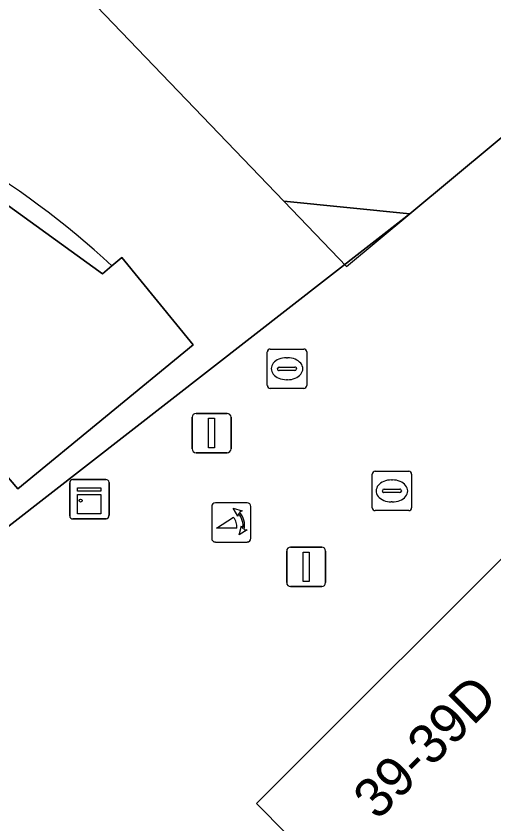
# Model space of a CAD drawing. Extents: x 161087 to 161926, y 382572 to 383873.
# Drawn here: x 161237.04 to 161249.19, y 383157.77 to 383178.3 of the extents above; entities that cross this region are included whole.
import ezdxf

# ---------------------------------------------------------------- set-up
doc = ezdxf.new("R2010")
doc.units = 0
for name, color, linetype in [('IMGEO_Kast', 7, 'Continuous'), ('IMGEO_Kolk', 7, 'Continuous'), ('IMGEO_Lichtmast', 7, 'Continuous'), ('IMGEO_Pand', 7, 'Continuous'), ('IMGEO_Pand_nummerreeks', 7, 'Continuous'), ('IMGEO_Pand_overbouw', 7, 'Continuous'), ('IMGEO_Poller', 7, 'Continuous'), ('IMGEO_Voetgangersgebied_open', 7, 'Continuous')]:
    doc.layers.add(name, color=color, linetype=linetype)

msp = doc.modelspace()

# ---------------------------------------------------------------- linework, layer by layer
at = {"layer": 'IMGEO_Kast'}
for p, q in [((161238.476, 383166.522), (161239.317, 383166.522)), ((161239.317, 383166.522), (161238.476, 383166.522)), ((161238.401, 383165.597), (161238.401, 383166.438)), ((161238.401, 383166.438), (161238.401, 383165.597)), ((161239.401, 383166.447), (161239.401, 383165.606)), ((161239.401, 383165.606), (161239.401, 383166.447)), ((161239.326, 383165.522), (161238.485, 383165.522)), ((161238.485, 383165.522), (161239.326, 383165.522))]:
    msp.add_line(p, q, dxfattribs=at)
for points in [[(161238.596, 383166.312), (161239.196, 383166.312), (161239.196, 383166.227), (161238.596, 383166.227), (161238.596, 383166.312)], [(161238.596, 383166.137), (161239.196, 383166.137), (161239.196, 383165.648), (161238.596, 383165.648), (161238.596, 383166.137)]]:
    msp.add_lwpolyline(points, dxfattribs=at)
msp.add_circle((161238.68, 383165.986), 0.0377, dxfattribs=at)
for centre, start, end in [((161238.479, 383166.444), 92.4484, 184.2845), ((161238.479, 383166.444), 92.4484, 184.2845), ((161239.323, 383166.444), 2.4484, 94.2845), ((161239.323, 383166.444), 2.4484, 94.2845), ((161238.479, 383165.6), 182.4484, 274.2845), ((161238.479, 383165.6), 182.4484, 274.2845), ((161239.323, 383165.6), 272.4484, 4.2845), ((161239.323, 383165.6), 272.4484, 4.2845)]:
    msp.add_arc(centre, 0.0779, start, end, dxfattribs=at)
at = {"layer": 'IMGEO_Kolk'}
for p, q in [((161243.502, 383169.839), (161244.354, 383169.839)), ((161243.427, 383168.913), (161243.427, 383169.765)), ((161243.915, 383169.619), (161243.94, 383169.619)), ((161244.428, 383169.765), (161244.428, 383168.913)), ((161243.686, 383169.333), (161243.686, 383169.345)), ((161244.124, 383169.296), (161243.726, 383169.296)), ((161243.729, 383169.382), (161244.127, 383169.382)), ((161244.17, 383169.345), (161244.17, 383169.333)), ((161243.938, 383169.059), (161243.913, 383169.059)), ((161244.354, 383168.839), (161243.502, 383168.839)), ((161246.169, 383166.732), (161247.021, 383166.732)), ((161246.094, 383165.806), (161246.094, 383166.658)), ((161246.582, 383166.512), (161246.607, 383166.512)), ((161247.095, 383166.658), (161247.095, 383165.806)), ((161246.353, 383166.226), (161246.353, 383166.238)), ((161246.791, 383166.189), (161246.393, 383166.189)), ((161246.396, 383166.275), (161246.794, 383166.275)), ((161246.837, 383166.238), (161246.837, 383166.226)), ((161246.605, 383165.952), (161246.58, 383165.952)), ((161247.021, 383165.732), (161246.169, 383165.732))]:
    msp.add_line(p, q, dxfattribs=at)
for points in [[(161243.502, 383169.839), (161244.354, 383169.839)], [(161243.427, 383168.913), (161243.427, 383169.765)], [(161244.428, 383169.765), (161244.428, 383168.913)], [(161244.354, 383168.839), (161243.502, 383168.839)], [(161246.169, 383166.732), (161247.021, 383166.732)], [(161246.094, 383165.806), (161246.094, 383166.658)], [(161247.095, 383166.658), (161247.095, 383165.806)], [(161247.021, 383165.732), (161246.169, 383165.732)]]:
    msp.add_lwpolyline(points, dxfattribs=at)
for centre, radius, start, end in [((161243.504, 383169.763), 0.0765, 91.552, 178.448), ((161243.504, 383169.763), 0.0765, 91.552, 178.448), ((161244.352, 383169.763), 0.0765, 1.552, 88.448), ((161244.352, 383169.763), 0.0765, 1.552, 88.448), ((161243.726, 383169.342), 0.0403, 85.8775, 175.7526), ((161243.723, 383169.332), 0.0366, 178.938, 274.7102), ((161244.127, 383169.339), 0.043, 264.8664, 352.4533), ((161244.131, 383169.344), 0.0386, 1.7309, 96.639), ((161243.504, 383168.915), 0.0765, 181.552, 268.448), ((161243.504, 383168.915), 0.0765, 181.552, 268.448), ((161244.352, 383168.915), 0.0765, 271.552, 358.448), ((161244.352, 383168.915), 0.0765, 271.552, 358.448), ((161246.171, 383166.656), 0.0765, 91.552, 178.448), ((161246.171, 383166.656), 0.0765, 91.552, 178.448), ((161247.019, 383166.656), 0.0765, 1.552, 88.448), ((161247.019, 383166.656), 0.0765, 1.552, 88.448), ((161246.393, 383166.235), 0.0403, 85.8775, 175.7526), ((161246.39, 383166.225), 0.0366, 178.938, 274.7102), ((161246.794, 383166.232), 0.043, 264.8664, 352.4533), ((161246.798, 383166.237), 0.0386, 1.7309, 96.639), ((161246.171, 383165.808), 0.0765, 181.552, 268.448), ((161246.171, 383165.808), 0.0765, 181.552, 268.448), ((161247.019, 383165.808), 0.0765, 271.552, 358.448), ((161247.019, 383165.808), 0.0765, 271.552, 358.448)]:
    msp.add_arc(centre, radius, start, end, dxfattribs=at)
for centre, major_axis, ratio, start_param, end_param in [((161243.914, 383169.339), (-0.387, 0.002), 0.722429, 4.712389, 7.853982), ((161243.939, 383169.339), (-0.39, 0.002), 0.717154, 1.570796, 4.712389), ((161246.581, 383166.232), (-0.387, 0.002), 0.722429, 4.712389, 7.853982), ((161246.606, 383166.232), (-0.39, 0.002), 0.717154, 1.570796, 4.712389)]:
    msp.add_ellipse(centre, major_axis=major_axis, ratio=ratio, start_param=start_param, end_param=end_param, dxfattribs=at)
at = {"layer": 'IMGEO_Lichtmast'}
for p, q in [((161241.614, 383168.203), (161242.404, 383168.203)), ((161242.404, 383168.203), (161241.614, 383168.203)), ((161241.514, 383167.303), (161241.514, 383168.103)), ((161241.514, 383168.103), (161241.514, 383167.303)), ((161242.504, 383168.103), (161242.504, 383167.303)), ((161242.504, 383167.303), (161242.504, 383168.103)), ((161242.404, 383167.203), (161241.614, 383167.203)), ((161241.614, 383167.203), (161242.404, 383167.203)), ((161243.919, 383163.902), (161243.919, 383164.702)), ((161243.919, 383164.702), (161243.919, 383163.902)), ((161244.019, 383164.802), (161244.809, 383164.802)), ((161244.809, 383164.802), (161244.019, 383164.802)), ((161244.909, 383164.702), (161244.909, 383163.902)), ((161244.909, 383163.902), (161244.909, 383164.702)), ((161244.809, 383163.802), (161244.019, 383163.802)), ((161244.019, 383163.802), (161244.809, 383163.802))]:
    msp.add_line(p, q, dxfattribs=at)
for points in [[(161241.934, 383168.078), (161242.084, 383168.078), (161242.084, 383167.328), (161241.934, 383167.328), (161241.934, 383168.078)], [(161244.339, 383164.677), (161244.489, 383164.677), (161244.489, 383163.927), (161244.339, 383163.927), (161244.339, 383164.677)]]:
    msp.add_lwpolyline(points, dxfattribs=at)
for centre, start, end in [((161241.614, 383168.103), 90, 180), ((161241.614, 383168.103), 90, 180), ((161242.404, 383168.103), 0, 90), ((161242.404, 383168.103), 360, 90), ((161241.614, 383167.303), 180, 270), ((161241.614, 383167.303), 180, 270), ((161242.404, 383167.303), 270, 0), ((161242.404, 383167.303), 270, 0), ((161244.019, 383164.702), 90, 180), ((161244.019, 383164.702), 90, 180), ((161244.809, 383164.702), 0, 90), ((161244.809, 383164.702), 360, 90), ((161244.019, 383163.902), 180, 270), ((161244.019, 383163.902), 180, 270), ((161244.809, 383163.902), 270, 0), ((161244.809, 383163.902), 270, 0)]:
    msp.add_arc(centre, 0.1, start, end, dxfattribs=at)
at = {"layer": 'IMGEO_Pand'}
msp.add_lwpolyline([(161254.221, 383238.815), (161229.145, 383218.076), (161229.277, 383217.916), (161227.113, 383216.127), (161228.197, 383214.816), (161214.888, 383203.681), (161215.678, 383202.854), (161218.189, 383200.227), (161217.903, 383200.032), (161218.273, 383199.528), (161218.664, 383199.808), (161220.954, 383201.444), (161227.023, 383192.911), (161226.063, 383192.108), (161243.848, 383173.6), (161247.047, 383173.276), (161266.225, 383189.236)], dxfattribs=at)
for points in [[(161239.474, 383171.955), (161239.238, 383171.755), (161235.305, 383174.589), (161233.171, 383175.565), (161230.894, 383176.283), (161228.405, 383177.068), (161227.184, 383174.609), (161235.132, 383166.432), (161236.122, 383167.398), (161236.438, 383167.031), (161237.08, 383166.288), (161241.544, 383169.944), (161239.725, 383172.168)], [(161258.837, 383156.265), (161250.478, 383165.598), (161243.155, 383158.284), (161246.206, 383155.197), (161248.463, 383152.913), (161251.359, 383149.983)]]:
    msp.add_lwpolyline(points, close=True, dxfattribs=at)
at = {"layer": 'IMGEO_Pand_overbouw'}
msp.add_lwpolyline([(161243.848, 383173.6), (161245.442, 383171.941), (161247.047, 383173.276)], close=True, dxfattribs=at)
at = {"layer": 'IMGEO_Poller'}
for p, q in [((161242.915, 383165.93), (161242.107, 383165.93)), ((161242.915, 383165.93), (161242.107, 383165.93)), ((161242.013, 383165.835), (161242.013, 383165.028)), ((161242.013, 383165.835), (161242.013, 383165.028)), ((161243.009, 383165.028), (161243.009, 383165.835)), ((161243.009, 383165.028), (161243.009, 383165.835)), ((161242.107, 383164.933), (161242.915, 383164.933)), ((161242.107, 383164.933), (161242.915, 383164.933))]:
    msp.add_line(p, q, dxfattribs=at)
for points in [[(161242.692, 383165.659), (161242.68, 383165.586), (161242.555, 383165.791)], [(161242.555, 383165.791), (161242.786, 383165.725), (161242.715, 383165.693)], [(161242.648, 383165.286), (161242.135, 383165.286), (161242.565, 383165.561)], [(161242.708, 383165.114), (161242.774, 383165.345), (161242.804, 383165.277)], [(161242.84, 383165.25), (161242.912, 383165.239), (161242.708, 383165.114)]]:
    msp.add_lwpolyline(points, dxfattribs=at)
for centre, radius, start, end in [((161242.107, 383165.835), 0.0946, 90, 180), ((161242.107, 383165.835), 0.0946, 90, 180), ((161242.915, 383165.835), 0.0946, 0, 90), ((161242.915, 383165.835), 0.0946, 0, 90), ((161242.334, 383165.346), 0.516, 349.3569, 42.2912), ((161242.32, 383165.336), 0.332, 351.3247, 42.4854), ((161242.334, 383165.346), 0.476, 351.7527, 41.1691), ((161242.107, 383165.028), 0.0946, 180, 270), ((161242.107, 383165.028), 0.0946, 180, 270), ((161242.915, 383165.028), 0.0946, 270, 0), ((161242.915, 383165.028), 0.0946, 270, 0)]:
    msp.add_arc(centre, radius, start, end, dxfattribs=at)
at = {"layer": 'IMGEO_Voetgangersgebied_open'}
for points in [[(161213.179, 383186.09), (161222.243, 383176.723), (161234.788, 383163.737), (161247.047, 383173.276), (161243.848, 383173.6), (161226.063, 383192.108)], [(161266.225, 383189.236), (161247.047, 383173.276), (161234.788, 383163.737), (161233.197, 383162.349), (161231.319, 383160.775), (161231.254, 383160.721), (161229.915, 383159.599), (161234.987, 383154.381), (161236.492, 383152.832), (161237.96, 383154.174), (161238.837, 383153.269), (161242.001, 383153.229), (161239.46, 383155.862), (161241.034, 383157.27), (161245.087, 383153.075), (161248.463, 383152.913), (161246.206, 383155.197), (161243.155, 383158.284), (161250.478, 383165.598)], [(161239.474, 383171.955), (161239.725, 383172.168), (161241.544, 383169.944), (161237.08, 383166.288), (161236.438, 383167.031), (161235.109, 383165.727), (161223.232, 383177.968), (161223.904, 383177.984)], [(161231.215, 383176.838), (161230.894, 383176.283), (161233.171, 383175.565), (161235.305, 383174.589), (161239.238, 383171.755), (161239.474, 383171.955)]]:
    msp.add_lwpolyline(points, dxfattribs=at)
msp.add_arc((161223.898, 383155.036), 22.997, 47.3664, 71.4476, dxfattribs=at)
msp.add_arc((161223.898, 383155.036), 22.997, 47.3664, 71.4476, dxfattribs=at)

# ---------------------------------------------------------------- texts
at = {"layer": 'IMGEO_Pand_nummerreeks'}
msp.add_text('39-39D', height=1, rotation=44.7652, dxfattribs=at).set_placement((161246.228, 383157.835))

doc.saveas('drawing.dxf')
